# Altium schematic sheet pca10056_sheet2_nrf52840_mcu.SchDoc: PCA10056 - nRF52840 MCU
size A3; Organization: Nordic Semiconductor; DocumentNumber: 2; SheetNumber: 2; SheetTotal: 7; CompanyName: Nordic Semiconductor
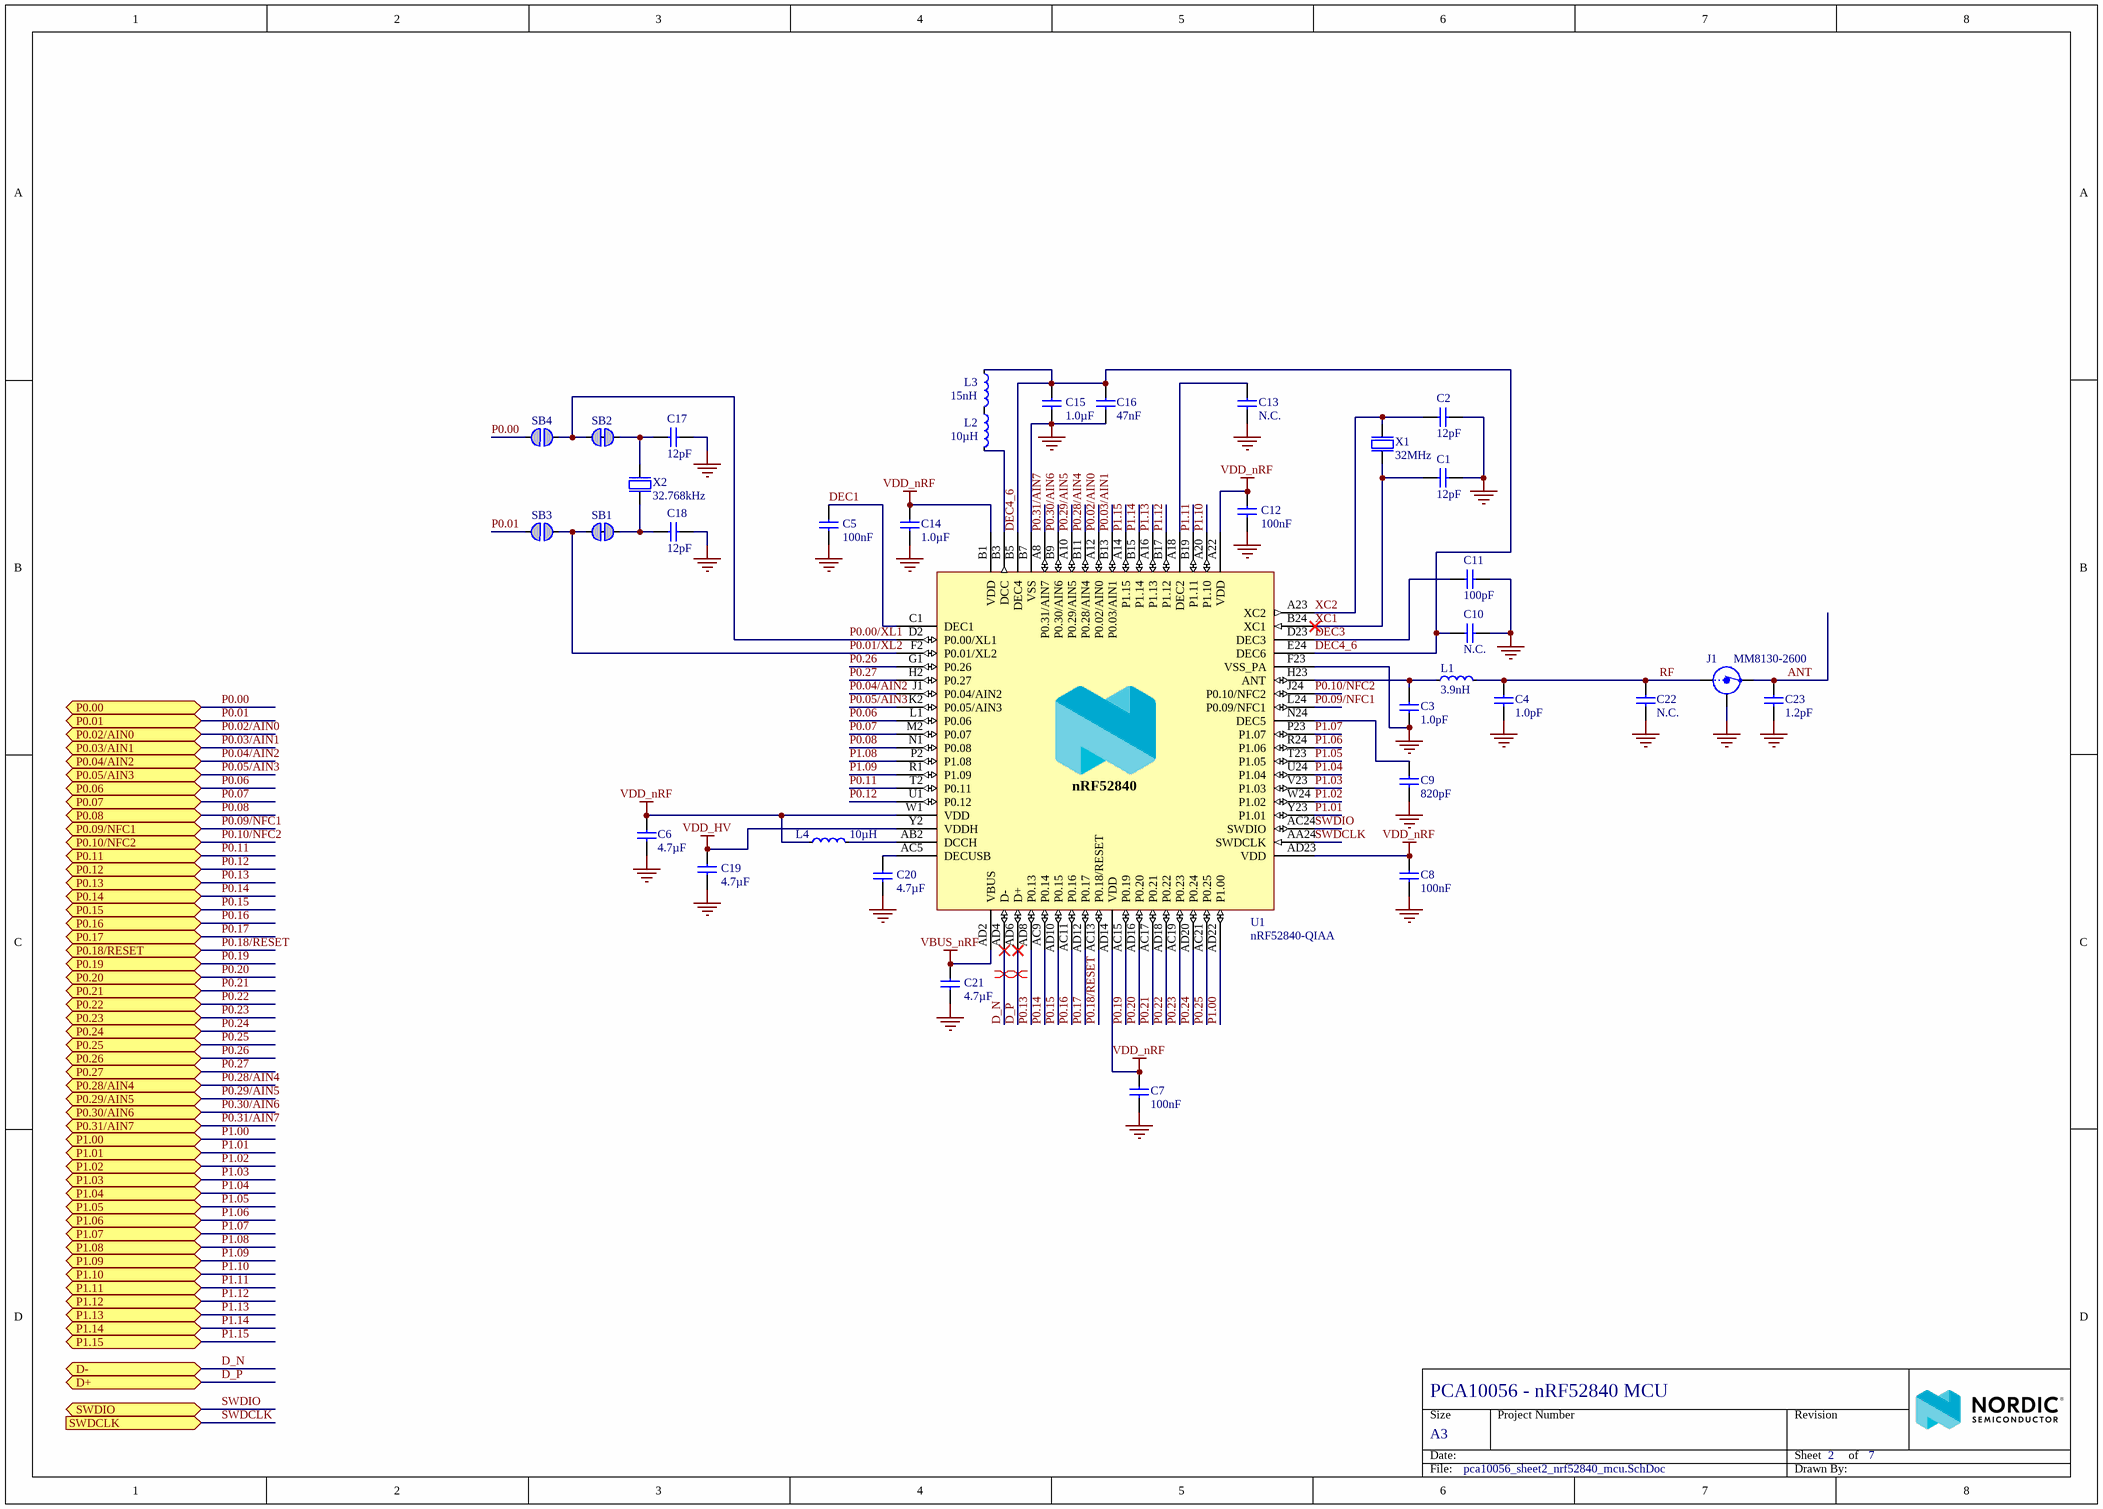
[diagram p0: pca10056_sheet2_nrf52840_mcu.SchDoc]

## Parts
C1  12pF  [CAPC1005X04L]
C2  12pF  [CAPC1005X04L]
C3  1.0pF  [CAPC1005X04L]
C4  1.0pF  [CAPC1005X04L]
C5  100nF  [CAPC1005X04L]
C6  4.7µF  [CAPC1608X06L]
C7  100nF  [CAPC1005X04L]
C8  100nF  [CAPC1005X04L]
C9  820pF  [CAPC1005X04L]
C10  N.C.  [CAPC1005X04L]
C11  100pF  [CAPC1005X04L]
C12  100nF  [CAPC1005X04L]
C13  N.C.  [CAPC1005X04L]
C14  1.0µF  [CAPC1608X06L]
C15  1.0µF  [CAPC1608X06L]
C16  47nF  [CAPC1005X04L]
C17  12pF  [CAPC1005X04L]
C18  12pF  [CAPC1005X04L]
C19  4.7µF  [CAPC1608X06L]
C20  4.7µF  [CAPC1608X06L]
C21  4.7µF  [CAPC1608X06L]
C22  N.C.  [CAPC1005X04L]
C23  1.2pF  [CAPC1005X04L]
J1  MM8130-2600  [COAXIAL-SWF]
L1  3.9nH  [INDC1005X04L]
L2  10µH  [INDC1608X06L]
L3  15nH  [INDC1005X04L]
L4  10µH  [INDC1608X06L]
SB1  Solderbridge  [Solderbridge_Shorted]  (value not drawn)  (net tie, no BOM)
SB2  Solderbridge  [Solderbridge_Shorted]  (value not drawn)  (net tie, no BOM)
SB3  Solderbridge  [Solderbridge]  (value not drawn)  (no BOM)
SB4  Solderbridge  [Solderbridge]  (value not drawn)  (no BOM)
U1  nRF52840-QIAA  [AQFN50P700X700X85_HS-74N]
X1  32MHz  [BT-XTAL_2016]
X2  32.768kHz  [XTAL_3215]

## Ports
D+ (bidir), D- (bidir), P0.00 (bidir), P0.01 (bidir), P0.02/AIN0 (bidir), P0.03/AIN1 (bidir), P0.04/AIN2 (bidir), P0.05/AIN3 (bidir), P0.06 (bidir), P0.07 (bidir), P0.08 (bidir), P0.09/NFC1 (bidir), P0.10/NFC2 (bidir), P0.11 (bidir), P0.12 (bidir), P0.13 (bidir), P0.14 (bidir), P0.15 (bidir), P0.16 (bidir), P0.17 (bidir), P0.18/RESET (bidir), P0.19 (bidir), P0.20 (bidir), P0.21 (bidir), P0.22 (bidir), P0.23 (bidir), P0.24 (bidir), P0.25 (bidir), P0.26 (bidir), P0.27 (bidir), P0.28/AIN4 (bidir), P0.29/AIN5 (bidir), P0.30/AIN6 (bidir), P0.31/AIN7 (bidir), P1.00 (bidir), P1.01 (bidir), P1.02 (bidir), P1.03 (bidir), P1.04 (bidir), P1.05 (bidir), P1.06 (bidir), P1.07 (bidir), P1.08 (bidir), P1.09 (bidir), P1.10 (bidir), P1.11 (bidir), P1.12 (bidir), P1.13 (bidir), P1.14 (bidir), P1.15 (bidir), SWDCLK (in), SWDIO (bidir)

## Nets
GND: C1.2 C2.2 C3.1 C4.1 C5.2 C6.2 C7.2 C8.2 C9.2 C10.1 C11.2 C12.2 C13.2 C14.2 C15.1 C16.2 C17.1 C18.1 C19.2 C20.2 C21.2 C22.2 C23.2 J1.2(Shield) U1.74(GND) U1.B7(VSS) U1.F23(VSS_PA) X1.2(GND) X1.4(GND)
VBUS_nRF: C21.1 U1.AD2(VBUS)
VDD_HV: C19.1 U1.Y2(VDDH)
VDD_nRF: C6.1 C7.1 C8.1 C12.1 C14.1 L4.1 U1.A22(VDD) U1.AD14(VDD) U1.AD23(VDD) U1.B1(VDD) U1.W1(VDD)
ANT: C23.1 J1.3(OUT)
D_N: U1.AD4(D-) ; port D-
D_P: U1.AD6(D+) ; port D+
DEC1: C5.1 U1.C1(DEC1)
DEC3: C11.1 U1.D23(DEC3)
DEC4_6: C10.2 C15.2 C16.1 L3.1 U1.B5(DEC4) U1.E24(DEC6)
P0.00: SB4.2 ; port P0.00
P0.00/XL1: SB2.2 SB4.1 U1.D2(P0.00/XL1)
P0.01: SB3.2 ; port P0.01
P0.01/XL2: SB1.2 SB3.1 U1.F2(P0.01/XL2)
P0.02/AIN0: U1.A12(P0.02/AIN0) ; port P0.02/AIN0
P0.03/AIN1: U1.B13(P0.03/AIN1) ; port P0.03/AIN1
P0.04/AIN2: U1.J1(P0.04/AIN2) ; port P0.04/AIN2
P0.05/AIN3: U1.K2(P0.05/AIN3) ; port P0.05/AIN3
P0.06: U1.L1(P0.06) ; port P0.06
P0.07: U1.M2(P0.07) ; port P0.07
P0.08: U1.N1(P0.08) ; port P0.08
P0.09/NFC1: U1.L24(P0.09/NFC1) ; port P0.09/NFC1
P0.10/NFC2: U1.J24(P0.10/NFC2) ; port P0.10/NFC2
P0.11: U1.T2(P0.11) ; port P0.11
P0.12: U1.U1(P0.12) ; port P0.12
P0.13: U1.AD8(P0.13) ; port P0.13
P0.14: U1.AC9(P0.14) ; port P0.14
P0.15: U1.AD10(P0.15) ; port P0.15
P0.16: U1.AC11(P0.16) ; port P0.16
P0.17: U1.AD12(P0.17) ; port P0.17
P0.18/RESET: U1.AC13(P0.18/RESET) ; port P0.18/RESET
P0.19: U1.AC15(P0.19) ; port P0.19
P0.20: U1.AD16(P0.20) ; port P0.20
P0.21: U1.AC17(P0.21) ; port P0.21
P0.22: U1.AD18(P0.22) ; port P0.22
P0.23: U1.AC19(P0.23) ; port P0.23
P0.24: U1.AD20(P0.24) ; port P0.24
P0.25: U1.AC21(P0.25) ; port P0.25
P0.26: U1.G1(P0.26) ; port P0.26
P0.27: U1.H2(P0.27) ; port P0.27
P0.28/AIN4: U1.B11(P0.28/AIN4) ; port P0.28/AIN4
P0.29/AIN5: U1.A10(P0.29/AIN5) ; port P0.29/AIN5
P0.30/AIN6: U1.B9(P0.30/AIN6) ; port P0.30/AIN6
P0.31/AIN7: U1.A8(P0.31/AIN7) ; port P0.31/AIN7
P1.00: U1.AD22(P1.00) ; port P1.00
P1.01: U1.Y23(P1.01) ; port P1.01
P1.02: U1.W24(P1.02) ; port P1.02
P1.03: U1.V23(P1.03) ; port P1.03
P1.04: U1.U24(P1.04) ; port P1.04
P1.05: U1.T23(P1.05) ; port P1.05
P1.06: U1.R24(P1.06) ; port P1.06
P1.07: U1.P23(P1.07) ; port P1.07
P1.08: U1.P2(P1.08) ; port P1.08
P1.09: U1.R1(P1.09) ; port P1.09
P1.10: U1.A20(P1.10) ; port P1.10
P1.11: U1.B19(P1.11) ; port P1.11
P1.12: U1.B17(P1.12) ; port P1.12
P1.13: U1.A16(P1.13) ; port P1.13
P1.14: U1.B15(P1.14) ; port P1.14
P1.15: U1.A14(P1.15) ; port P1.15
RF: C4.2 C22.1 J1.1(IN) L1.2
SWDCLK: U1.AA24(SWDCLK) ; port SWDCLK
SWDIO: U1.AC24(SWDIO) ; port SWDIO
XC1: C1.1 U1.B24(XC1) X1.1(inp)
XC2: C2.1 U1.A23(XC2) X1.3(out)
NetC3_2: C3.2 L1.1 U1.H23(ANT)
NetC9_1: C9.1 U1.N24(DEC5)
NetC13_1: C13.1 U1.A18(DEC2)
NetC17_2: C17.2 SB2.1 X2.1(inp)
NetC18_2: C18.2 SB1.1 X2.2(out)
NetC20_1: C20.1 U1.AC5(DECUSB)
NetL2_1: L2.1 L3.2
NetL2_2: L2.2 U1.B3(DCC)
NetL4_2: L4.2 U1.AB2(DCCH)

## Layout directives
differential pair: D_N, D_P

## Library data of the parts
C1 C2 C17 C18 = C0402-12p: Capacitor, NP0, ±2%; Part number IPS: 00000002398; Note: 50V; Artikkelnr Noca: 20029159; Artikkelnr Simpro: N.A.
C3 C4 = C0402-1.0p: Capacitor, NP0, ±0.1pF; Note: 50V; Artikkelnr Noca: 20029140; Artikkelnr Simpro: N.A.
C5 C7 C8 C12 = C0402-100n: Capacitor, X7R, ±10%; Part number IPS: 00000005296; Note: 16V; Artikkelnr Noca: 20039200; Artikkelnr Simpro: N.A.
C6 C20 = C0603-4µ7-6.3V-X7R: Capacitor, X7R, ±10%; Manufacturer: Samsung; Manufacturer Part Number: CL10B475KQ8NQNC; Note: 6.3V; Artikkelnr Noca: 20039473; Artikkelnr Simpro: N.A.
C9 = C0402-820p: Capacitor, NP0, ±5%; Note: 50V; Artikkelnr Noca: 20029219; Artikkelnr Simpro: N.A.
C10 C13 = C0402-N.C.: Not mounted; Note: Chip Cap; Assembly: Not mounted; Artikkelnr Noca: N.A.
C11 = C0402-100p: Capacitor, NP0, ±5%; Part number IPS: 00000002361; Note: 50V; Artikkelnr Noca: 20029135; Artikkelnr Simpro: N.A.
C14 C15 = C0603-1µ0: Capacitor, X7R, ±10%; Part number IPS: 00000000616; Note: 16V; Artikkelnr Noca: 20039335; Artikkelnr Simpro: N.A.
C16 = C0402-47n: Capacitor, X7R, ±10%; Note: Chip Cap 10%; Artikkelnr Noca: 20039389; Artikkelnr Simpro: N.A.
C19 C21 = C0603-4µ7-10V-X7S: Capacitor, X7S, ±10%; Note: 10V; Artikkelnr Noca: 20030013; Artikkelnr Simpro: N.A.
C22 = C0402-N.C.: Not mounted; Note: Chip Cap; Artikkelnr Noca: N.A.; Assembly: Not mounted
C23 = C0402-1.2p: Capacitor, NP0, ±0.1pF; Part number IPS: 00000005410; Note: 50V; Artikkelnr Noca: 20029157; Artikkelnr Simpro: N.A.
J1 = MM8130-2600: Coaxial Connector with Switch; Manufacturer: Murata; 2nd source part number: 81-MM8130-2600RA2; Artikkelnr Noca: 55029011; Artikkelnr Simpro: N.A.
L1 = L0402-3n9: Inductor, 170mA, ±0.1nH; Manufacturer: Murata; Manufacturer Part Number: LQP15MN3N9B02D; Part number IPS: 00000007793; Note: High frequency chip inductor ±5%; Artikkelnr Noca: 33029151; Artikkelnr Simpro: N.A.
L2 L4 = L0603-10µ: Inductor, 80mA, ±10%; Manufacturer: Taiyo Yuden; Manufacturer Part Number: LBMF1608T100K; 2nd source part number: 178-6105; Part number IPS: 00000007794; Note: LBMF1608T100K 10µH 80mA 0603; Artikkelnr Noca: 33029314; Artikkelnr Simpro: N.A.
L3 = L0402-15n: Inductor, 320mA, ±5%; Manufacturer: Taiyo Yuden; Manufacturer Part Number: HK100515NJ-T; 2nd source part number: 658-1328; Part number IPS: 00000003215; Note: High frequency chip inductor ±10%; Artikkelnr Noca: 33029323; Artikkelnr Simpro: N.A.
SB1 SB2 = Solderbridge Shorted: Shorted Solderbridge; Artikkelnr Noca: N.A.
SB3 SB4 = Solderbridge: Artikkelnr Noca: N.A.
U1 = nRF52840-QIAAC0: Multi-protocol Bluetooth Low Energy, IEEE 802.15.4, ANT and 2.4GHz proprietary system-on-chip; Manufacturer: Nordic Semiconductor; Artikkelnr Noca: 15079380; Artikkelnr Simpro: N.A.
X1 = XTAL_SMD2016_32MHz_8pF_Golledge: XTAL SMD 2016, 32MHz, Cl=8pF, Tol: ±10ppm, Stab: ±15ppm; Manufacturer Part Number: MP06003; Note: XTAL SMD 32.000MHz; Artikkelnr Noca: N.A.
X2 = XTAL_SMD3215_32.768kHz_9pF_NDK: XTAL SMD 2012, 32.768kHz, 9pF, ±20ppm; Manufacturer: NDK; Manufacturer Part Number: NX3215SA-32.768K-STD-MUA-9; Note: XTAL SMD 32.768kHz; Artikkelnr Noca: N.A.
